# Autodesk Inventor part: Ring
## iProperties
Created: 2009-03
Part Number: Ring
Document SubType Name: Modeling
Designer: tangg
Density: 7.86 g/cm^3
Material: Steel, Mild
Mass: 47.3376 g
Surface Area: 38.1795 cm^2
Volume: 6.02259 cm^3
Author: tangg
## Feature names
1. Extrusion1
